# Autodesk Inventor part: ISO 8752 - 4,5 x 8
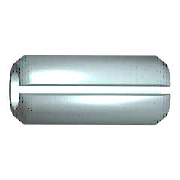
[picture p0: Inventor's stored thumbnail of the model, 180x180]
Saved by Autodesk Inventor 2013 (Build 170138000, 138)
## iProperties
Created: 2012-02
Part Number: ISO 8752 - 4,5 x 8
Material: Edelstahl, austenitisch
Description: Spannstift
Document SubType Name: Modeling
Standard: ISO 8752
Designer: rYan
Standards Organization: DIN
Language: de-DE
Size Designation: 4,5 x 8
Categories: <MemberInstance><Categories><Category DisplayName="Verbindungselemente" InternalName="e4da775c-781d-43d5-af7c-5136215cf5a6" Mnemonic="FSTN"><Category DisplayNam
Density: 8.03 g/cm^3
Mass: 0.77376 g
Surface Area: 2.31713 cm^2
Volume: 0.0963587 cm^3
IsCustomPart: 0
Author: rYan
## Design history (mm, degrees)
sketch "Skizze1"
  geometry: L1 (0, 1.55)-(0, 2.336); L2 (0, 2.336)-(0.8, 2.55); L3 (0.8, 2.55)-(7.2, 2.55); L4 (7.2, 2.55)-(8, 2.336); L5 (8, 2.336)-(8, 1.55); L6 (8, 0)-(0, 0); L7 (0, 1.55)-(8, 1.55); L8 (0, 1.55)-(0, 0); L9 (8, 1.55)-(8, 0); L10 (0, 1.68)-(0, -0.28) reference; L11 (-2, 0)-(12, 0) reference
  constraints: 18 end point, 3 parallel, 3 perpendicular, 1 coincident, 1 point on line, 1 vertical
  dimensions: "d0" = 8 distance between parallel lines of L5 L1 (= NLG); "d1" = 5.1 diameter of L3 L6 (= NND1); "d2" = 3.1 diameter of L7 L6 (= NND1 - 2 x SD); "d3" = 15 deg angle of L3 L2 (= FAWI); "d4" = 15 deg angle of L4 L3 (= FAWI); "d7" = 0.21436 vertical distance of L2.end L1.end (computed from SD, FAWI, PHH); "d8" = 0.21436 vertical distance of L3.end L4.end (computed from SD, FAWI, PHH1)
revolve "Körper" sketch "Skizze1" stored, may be unused: angle "d10" = 90 deg
workplane "Work Plane1"
sketch "Skizze2"
  geometry: L1 (-0.194, 1.538)-(-0.32, 2.53); L2 (0.194, 1.538)-(0.32, 2.53); L3 (0, 1.68)-(0, -0.28) reference; L4 (-0.246, 0)-(0.246, 0) reference; A1 r 2.55 centre (0, 0) between (0.32, 2.53) and (-0.32, 2.53); A2 r 1.55 centre (0, 0) between (0.194, 1.538) and (-0.194, 1.538); 1 further point
  constraints: 4 end point, 4 point on circle, 2 centre point, 2 coincident, 2 horizontal alignment, 1 other
  dimensions: "d11" = 2.55 radius of A1 (= 0.5 x NND1); "d12" = 1.55 radius of A2 (= -SD + 0.5 x NND1); "d14" = 1 distance of L1.start L1.end (= SD); "d15" = 7.2 deg angle of L3 L1
extrude "Schnitt" cut sketch "Skizze2" stored distance "d5" = 8 (= NLG); taper "d6" = 0 deg
body "Solid1"
other parameters: "NND" = 4.5 [user parameter], "NLG" = 8 [user parameter; used in 3 equation terms], "SD" = 1 [user parameter; used in 5 equation terms], "PHH" = 0.8 [user parameter; used in 2 equation terms], "PHH1" = 0.8 (= PHH) [user parameter; used in 1 equation term], "FAWI" = 15 deg [user parameter; used in 4 equation terms], "d9" = 4 (= 0.5 x NLG), "d31" = 0, "d32" = 0, "d33" = 0, "NND1" = 5.1 [user parameter; used in 4 equation terms]
